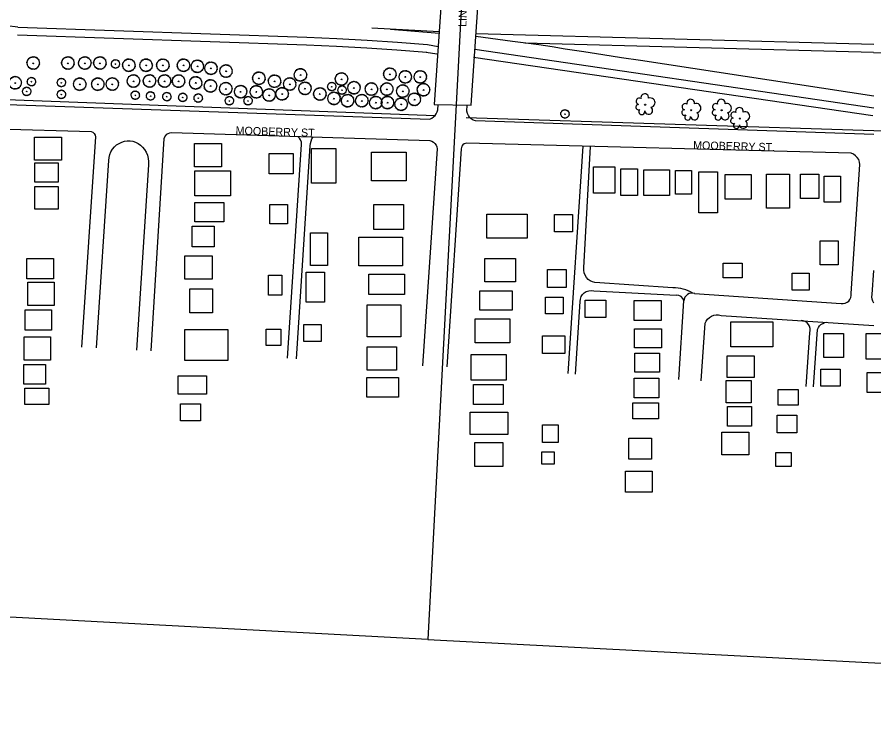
# Model space of a CAD drawing. Extents: x -9648 to 41057, y -12373 to 40276.
# Drawn here: x 13475 to 14546, y -5975 to -5099 of the extents above; entities that cross this region are included whole.
import ezdxf

# ---------------------------------------------------------------- set-up
doc = ezdxf.new("R2010")
doc.units = 0
for name, color, linetype in [('Default', 7, 'Continuous'), ('SC_Scratch1', 7, 'Continuous'), ('SH_Data', 7, 'Continuous')]:
    doc.layers.add(name, color=color, linetype=linetype)

# ---------------------------------------------------------------- blocks, each defined once
blk = doc.blocks.new('15_PIN')
at = {"layer": 'Default'}
for p, q in [((-2.8, 0), (2.8, 0)), ((0, 2.8), (0, -2.8))]:
    blk.add_line(p, q, dxfattribs=at)
for centre, start, end in [((-25.5, 4.5), 275.99, 64.01), ((-25.9, -1.5), 289.3234, 77.3433), ((-23.8, 10.3), 262.6567, 50.6766), ((-20.8, 15.5), 249.3234, 37.3433), ((-16.7, 19.8), 235.99, 24.01), ((-11.6, 23.2), 222.6567, 10.6766), ((-6, 25.2), 209.3234, 357.3433), ((0, 25.9), 195.99, 344.01), ((6, 25.2), 182.6567, 330.6766), ((11.6, 23.2), 169.3234, 317.3433), ((16.7, 19.8), 155.99, 304.01), ((20.8, 15.5), 142.6567, 290.6766), ((23.8, 10.3), 129.3234, 277.3433), ((25.5, 4.5), 115.99, 264.01), ((25.9, -1.5), 102.6567, 250.6766), ((-24.8, -7.4), 302.6567, 90.6766), ((-22.4, -13), 315.99, 104.01), ((-18.8, -17.8), 329.3234, 117.3433), ((-14.2, -21.6), 342.6567, 130.6766), ((-8.9, -24.3), 355.99, 144.01), ((-3, -25.7), 9.3234, 157.3433), ((3, -25.7), 22.6567, 170.6766), ((8.9, -24.3), 35.99, 184.01), ((14.2, -21.6), 49.3234, 197.3433), ((18.8, -17.8), 62.6567, 210.6767), ((22.4, -13), 75.99, 224.01), ((24.8, -7.4), 89.3234, 237.3433)]:
    blk.add_arc(centre, 3.05, start, end, dxfattribs=at)

msp = doc.modelspace()

# ---------------------------------------------------------------- linework, layer by layer
at = {"layer": 'SC_Scratch1'}
for p, q in [((14069.8, -4338.8), (13988.6, -5876.7)), ((14069.8, -4338.8), (13988.6, -5876.7)), ((14069.8, -4338.8), (13988.6, -5876.7)), ((13988.6, -5876.7), (12411.7, -5793.4)), ((13988.6, -5876.7), (15846.2, -5974.8))]:
    msp.add_line(p, q, dxfattribs=at)
at = {"layer": 'SH_Data'}
for p, q in [((14016.7, -4912.3), (13996.7, -5208.5)), ((14042.7, -5209.3), (14062.9, -4912.9)), ((13476.1, -5111.5), (13462.3, -5110)), ((13476.1, -5111.5), (13837.3, -5124.3)), ((13918.7, -5112.5), (14002.9, -5117.1)), ((14002.7, -5119.4), (13941.9, -5114.7)), ((13836.9, -5134.3), (13475.7, -5121.5)), ((13837.3, -5124.3), (13875.1, -5125.9)), ((13875.1, -5125.9), (13912.9, -5127.9)), ((13912.9, -5127.9), (13950.6, -5130.5)), ((14094.5, -5129.7), (14048.6, -5123.5)), ((14546.1, -5133.5), (14048.8, -5119.9)), ((13874.7, -5135.9), (13836.9, -5134.3)), ((13912.3, -5137.8), (13874.5, -5135.8)), ((13949.9, -5140.4), (13912.2, -5137.8)), ((13950.6, -5130.5), (13988.3, -5133.5)), ((13988.3, -5133.5), (14001.6, -5135.7)), ((14111, -5131.7), (14094.5, -5129.7)), ((14545.8, -5143.5), (14110, -5131.5)), ((14127.5, -5133.9), (14111, -5131.7)), ((14143.9, -5136.4), (14127.5, -5133.9)), ((14160.3, -5139.1), (14143.9, -5136.4)), ((14183.8, -5142.6), (14160.3, -5139.1)), ((13987.5, -5143.4), (13949.8, -5140.4)), ((13999.9, -5145.5), (13986.6, -5143.3)), ((14544.6, -5222.6), (14045.9, -5149.6)), ((14546.1, -5212.7), (14047.4, -5139.7)), ((14207.3, -5146.1), (14183.8, -5142.6)), ((14230.8, -5149.8), (14207.3, -5146.1)), ((14254.3, -5153.5), (14230.8, -5149.8)), ((14545.8, -5143.5), (15004.6, -5156.7)), ((14546.1, -5197.7), (14254.3, -5153.5)), ((12857.6, -5180.1), (13997.6, -5221.9)), ((12865.7, -5187.5), (13991.1, -5226.5)), ((13996.7, -5208.5), (14042.7, -5209.3)), ((14001.3, -5214.9), (14001.7, -5208.6)), ((14037.5, -5216.7), (14037.7, -5209.2)), ((13993.5, -5225.3), (13995.7, -5223.8)), ((13995.7, -5223.8), (13997.6, -5222)), ((13997.6, -5222), (13999.2, -5219.8)), ((13999.2, -5219.8), (14000.5, -5217.4)), ((14000.5, -5217.4), (14001.3, -5214.9)), ((14036.6, -5224.5), (14559, -5241.4)), ((14038.1, -5219.5), (14037.5, -5216.7)), ((14039.3, -5222), (14038.1, -5219.5)), ((14040.9, -5224.3), (14039.3, -5222)), ((14043, -5226.3), (14040.9, -5224.3)), ((13212.5, -5232.9), (13567.7, -5241.9)), ((13991.1, -5226.5), (13993.5, -5225.3)), ((14045.4, -5227.7), (14043, -5226.3)), ((14048.1, -5228.7), (14045.4, -5227.7)), ((14546.1, -5245.9), (14048.1, -5228.7)), ((13567.7, -5241.9), (13569.9, -5242.9)), ((13569.9, -5242.9), (13571.7, -5244.5)), ((13571.7, -5244.5), (13572.8, -5246.5)), ((13572.8, -5246.5), (13573.3, -5248.9)), ((13661, -5247.1), (13662.5, -5245.5)), ((13662.5, -5245.5), (13664.2, -5244.4)), ((13664.2, -5244.4), (13666.2, -5243.6)), ((13666.2, -5243.6), (13668.3, -5243.3)), ((13668.3, -5243.3), (13991.1, -5253.3)), ((13573.3, -5248.9), (13556, -5511.6)), ((13599.7, -5258.9), (13602.7, -5256.9)), ((13602.7, -5256.9), (13606.1, -5255.3)), ((13606.1, -5255.3), (13609.5, -5254.3)), ((13609.5, -5254.3), (13613, -5253.7)), ((13613, -5253.7), (13616.5, -5253.8)), ((13616.5, -5253.8), (13620, -5254.3)), ((13620, -5254.3), (13623.3, -5255.4)), ((13623.3, -5255.4), (13626.5, -5257)), ((13626.5, -5257), (13629.4, -5259)), ((13642.7, -5516.3), (13659.3, -5250.9)), ((13659.3, -5250.9), (13659.9, -5248.9)), ((13659.9, -5248.9), (13661, -5247.1)), ((13828.1, -5250.2), (13826, -5248.2)), ((13829.6, -5252.6), (13828.1, -5250.2)), ((13830.6, -5255.3), (13829.6, -5252.6)), ((13830.9, -5258.1), (13830.6, -5255.3)), ((13841.7, -5259.9), (13842, -5256.9)), ((13842, -5256.9), (13842.7, -5254.1)), ((13842.7, -5254.1), (13843.8, -5251.3)), ((13843.8, -5251.3), (13845.3, -5248.8)), ((13991.1, -5253.3), (13993.5, -5254)), ((13993.5, -5254), (13995.7, -5255.2)), ((13995.7, -5255.2), (13997.5, -5257)), ((13997.5, -5257), (13998.9, -5259)), ((14035.6, -5256.9), (14033.9, -5257.6)), ((14037.5, -5256.7), (14035.6, -5256.9)), ((14517.7, -5269.3), (14037.5, -5256.7)), ((13591.2, -5270.8), (13592.6, -5267.4)), ((13592.6, -5267.4), (13594.5, -5264.2)), ((13594.5, -5264.2), (13596.9, -5261.4)), ((13596.9, -5261.4), (13599.7, -5258.9)), ((13629.4, -5259), (13631.9, -5261.5)), ((13631.9, -5261.5), (13634.5, -5264.6)), ((13634.5, -5264.6), (13636.7, -5268)), ((13813.3, -5525.5), (13830.9, -5258.1)), ((13824.4, -5526.1), (13841.7, -5259.9)), ((14000.1, -5263.9), (13982.1, -5534.7)), ((13998.9, -5259), (13999.8, -5261.4)), ((13999.8, -5261.4), (14000.1, -5263.9)), ((14030.5, -5263.9), (14012.2, -5536.3)), ((14030.7, -5262), (14030.5, -5263.9)), ((14031.3, -5260.3), (14030.7, -5262)), ((14032.4, -5258.8), (14031.3, -5260.3)), ((14033.9, -5257.6), (14032.4, -5258.8)), ((14182.2, -5260.5), (14163.5, -5544.5)), ((14183.7, -5412.3), (14191.9, -5260.7)), ((13574.4, -5512.6), (13589.9, -5278.1)), ((13589.9, -5278.1), (13590.3, -5274.4)), ((13590.3, -5274.4), (13591.2, -5270.8)), ((13636.7, -5268), (13638.3, -5271.7)), ((13638.3, -5271.7), (13639.3, -5275.6)), ((13639.3, -5275.6), (13639.7, -5279.7)), ((14520.6, -5270.5), (14517.7, -5269.3)), ((14523.2, -5272.3), (14520.6, -5270.5)), ((14525.4, -5274.6), (14523.2, -5272.3)), ((14527.1, -5277.2), (14525.4, -5274.6)), ((14528.2, -5280.2), (14527.1, -5277.2)), ((13639.5, -5283.7), (13624.5, -5515.3)), ((13639.7, -5279.7), (13639.5, -5283.7)), ((14517.9, -5444.7), (14528.7, -5283.3)), ((14528.7, -5283.3), (14528.2, -5280.2)), ((14183.6, -5415.5), (14183.7, -5412.3)), ((14184.1, -5418.6), (14183.6, -5415.5)), ((14544.1, -5445.9), (14546.1, -5415.7)), ((14185.2, -5421.7), (14184.1, -5418.6)), ((14186.8, -5424.4), (14185.2, -5421.7)), ((14189, -5426.8), (14186.8, -5424.4)), ((14191.5, -5428.7), (14189, -5426.8)), ((14194.4, -5430.1), (14191.5, -5428.7)), ((14197.5, -5430.9), (14194.4, -5430.1)), ((14294.9, -5437.3), (14197.5, -5430.9)), ((14179.3, -5451.4), (14180.3, -5448.4)), ((14180.3, -5448.4), (14181.9, -5445.8)), ((14181.9, -5445.8), (14184.1, -5443.5)), ((14184.1, -5443.5), (14186.7, -5441.9)), ((14186.7, -5441.9), (14189.7, -5441)), ((14189.7, -5441), (14192.8, -5440.8)), ((14192.8, -5440.8), (14195.9, -5441.3)), ((14195.9, -5441.3), (14298.9, -5446.5)), ((14322.1, -5444.3), (14505.3, -5457.1)), ((14516.2, -5452), (14517.3, -5449.7)), ((14517.3, -5449.7), (14517.9, -5447.2)), ((14517.9, -5447.2), (14517.9, -5444.7)), ((14543.7, -5448.7), (14544.1, -5445.9)), ((14543.9, -5451.4), (14543.7, -5448.7)), ((14173.1, -5545.1), (14179.1, -5454.5)), ((14179.1, -5454.5), (14179.3, -5451.4)), ((14302.4, -5552.1), (14308.7, -5453.7)), ((14505.3, -5457.1), (14507.8, -5457.1)), ((14507.8, -5457.1), (14510.3, -5456.6)), ((14510.3, -5456.6), (14512.6, -5455.5)), ((14512.6, -5455.5), (14514.6, -5453.9)), ((14514.6, -5453.9), (14516.2, -5452)), ((14544.7, -5454.1), (14543.9, -5451.4)), ((14546.1, -5456.5), (14544.7, -5454.1)), ((14346, -5471.7), (14349, -5471.1)), ((14349, -5471.1), (14352.1, -5471.2)), ((14352.1, -5471.2), (14355.1, -5471.9)), ((14330.2, -5553.6), (14335.1, -5481.7)), ((14335.1, -5481.7), (14336.4, -5478.9)), ((14336.4, -5478.9), (14338.2, -5476.4)), ((14338.2, -5476.4), (14340.5, -5474.3)), ((14340.5, -5474.3), (14343.1, -5472.7)), ((14343.1, -5472.7), (14346, -5471.7)), ((14355.1, -5471.9), (14546.1, -5484.3)), ((14457.9, -5478.5), (14455.2, -5478.1)), ((14460.4, -5479.5), (14457.9, -5478.5)), ((14462.6, -5481.1), (14460.4, -5479.5)), ((14464.4, -5483.1), (14462.6, -5481.1)), ((14480, -5483.4), (14482.1, -5482)), ((14482.1, -5482), (14484.3, -5480.9)), ((14484.3, -5480.9), (14486.7, -5480.2)), ((14465.7, -5485.5), (14464.4, -5483.1)), ((14466.4, -5488.1), (14465.7, -5485.5)), ((14465.9, -5493.5), (14466.5, -5490.8)), ((14466.5, -5490.8), (14466.4, -5488.1)), ((14470.7, -5561.2), (14475.7, -5489.3)), ((14475.7, -5489.3), (14476.8, -5487.1)), ((14476.8, -5487.1), (14478.2, -5485.1)), ((14478.2, -5485.1), (14480, -5483.4)), ((14461.5, -5560.7), (14465.9, -5493.5))]:
    msp.add_line(p, q, dxfattribs=at)
for points in [[(13497, -5249.3), (13530.8, -5249.3), (13530.8, -5277.7), (13497, -5277.7)], [(13696.9, -5256.9), (13730.6, -5256.9), (13730.6, -5286.1), (13696.9, -5286.1)], [(13843.1, -5263.2), (13873.6, -5263.2), (13873.6, -5306.5), (13843.1, -5306.5)], [(13918.1, -5267.7), (13961.4, -5267.7), (13961.4, -5303.9), (13918.1, -5303.9)], [(13790.3, -5269.6), (13820.2, -5269.6), (13820.2, -5295), (13790.3, -5295)], [(13497.6, -5281.3), (13526.6, -5281.3), (13526.6, -5305.5), (13497.6, -5305.5)], [(14195.5, -5286.1), (14222.3, -5286.1), (14222.3, -5319.3), (14195.5, -5319.3)], [(14229.8, -5288.7), (14250.7, -5288.7), (14250.7, -5322), (14229.8, -5322)], [(13697.5, -5291.2), (13742, -5291.2), (13742, -5322.4), (13697.5, -5322.4)], [(14258.7, -5289.8), (14290.8, -5289.8), (14290.8, -5322), (14258.7, -5322)], [(14298.3, -5290.9), (14318.1, -5290.9), (14318.1, -5320.3), (14298.3, -5320.3)], [(14327.2, -5292.5), (14350.8, -5292.5), (14350.8, -5343.9), (14327.2, -5343.9)], [(14360.4, -5295.7), (14392.6, -5295.7), (14392.6, -5326.8), (14360.4, -5326.8)], [(14411.8, -5295.2), (14440.8, -5295.2), (14440.8, -5338), (14411.8, -5338)], [(14454.2, -5295.2), (14477.2, -5295.2), (14477.2, -5325.7), (14454.2, -5325.7)], [(14484.1, -5297.9), (14504.5, -5297.9), (14504.5, -5330.5), (14484.1, -5330.5)], [(13497.6, -5310.9), (13526.6, -5310.9), (13526.6, -5339.3), (13497.6, -5339.3)], [(13697.5, -5330.6), (13733.7, -5330.6), (13733.7, -5354.8), (13697.5, -5354.8)], [(13791, -5333.2), (13813.2, -5333.2), (13813.2, -5357.4), (13791, -5357.4)], [(13921.3, -5333.2), (13958.2, -5333.2), (13958.2, -5364.4), (13921.3, -5364.4)], [(14062.4, -5345.3), (14112.7, -5345.3), (14112.7, -5375.2), (14062.4, -5375.2)], [(14147, -5345.9), (14169.3, -5345.9), (14169.3, -5367.5), (14147, -5367.5)], [(13694.3, -5360.5), (13721.7, -5360.5), (13721.7, -5386), (13694.3, -5386)], [(13841.8, -5368.8), (13863.4, -5368.8), (13863.4, -5409.5), (13841.8, -5409.5)], [(13902.2, -5373.9), (13956.9, -5373.9), (13956.9, -5410.1), (13902.2, -5410.1)], [(14478.8, -5378.7), (14501.3, -5378.7), (14501.3, -5408.7), (14478.8, -5408.7)], [(13487.4, -5400.9), (13520.6, -5400.9), (13520.6, -5426.3), (13487.4, -5426.3)], [(13684.8, -5397.4), (13719.1, -5397.4), (13719.1, -5426.7), (13684.8, -5426.7)], [(14059.9, -5400.6), (14098.1, -5400.6), (14098.1, -5429.9), (14059.9, -5429.9)], [(14357.8, -5406.6), (14381.3, -5406.6), (14381.3, -5424.8), (14357.8, -5424.8)], [(13836.7, -5417.8), (13859.6, -5417.8), (13859.6, -5455.3), (13836.7, -5455.3)], [(14138.1, -5414.6), (14161.6, -5414.6), (14161.6, -5436.9), (14138.1, -5436.9)], [(13789.7, -5421.6), (13806.2, -5421.6), (13806.2, -5446.4), (13789.7, -5446.4)], [(13914.9, -5420.3), (13959.4, -5420.3), (13959.4, -5445.8), (13914.9, -5445.8)], [(14444, -5418.9), (14465.4, -5418.9), (14465.4, -5440.3), (14444, -5440.3)], [(13488.6, -5430.5), (13521.8, -5430.5), (13521.8, -5459.5), (13488.6, -5459.5)], [(13691.1, -5438.8), (13719.7, -5438.8), (13719.7, -5468.7), (13691.1, -5468.7)], [(14053.5, -5441.3), (14094.2, -5441.3), (14094.2, -5465.5), (14053.5, -5465.5)], [(14135.6, -5448.9), (14157.8, -5448.9), (14157.8, -5469.9), (14135.6, -5469.9)], [(13913, -5458.5), (13955, -5458.5), (13955, -5498.6), (13913, -5498.6)], [(14185.3, -5452.7), (14211, -5452.7), (14211, -5474.6), (14185.3, -5474.6)], [(14246.4, -5453.2), (14280.1, -5453.2), (14280.1, -5478.4), (14246.4, -5478.4)], [(13485.5, -5465), (13518.2, -5465), (13518.2, -5490.3), (13485.5, -5490.3)], [(14047.8, -5476.3), (14091.1, -5476.3), (14091.1, -5506.2), (14047.8, -5506.2)], [(14367.4, -5480), (14419.9, -5480), (14419.9, -5511), (14367.4, -5511)], [(13684.8, -5489.6), (13738.8, -5489.6), (13738.8, -5528.4), (13684.8, -5528.4)], [(13786.5, -5489), (13804.9, -5489), (13804.9, -5509.4), (13786.5, -5509.4)], [(13833.6, -5483.3), (13855.2, -5483.3), (13855.2, -5504.3), (13833.6, -5504.3)], [(14246.9, -5488.5), (14280.7, -5488.5), (14280.7, -5512.6), (14246.9, -5512.6)], [(13484.3, -5498.8), (13516.9, -5498.8), (13516.9, -5527.8), (13484.3, -5527.8)], [(14131.8, -5497.3), (14159.7, -5497.3), (14159.7, -5519.5), (14131.8, -5519.5)], [(14483.6, -5494.4), (14508.2, -5494.4), (14508.2, -5524.4), (14483.6, -5524.4)], [(14536.6, -5494.4), (14591.8, -5494.4), (14591.8, -5526.6), (14536.6, -5526.6)], [(13913, -5511.3), (13949.3, -5511.3), (13949.3, -5540.5), (13913, -5540.5)], [(14042.7, -5520.8), (14086.6, -5520.8), (14086.6, -5552.6), (14042.7, -5552.6)], [(14247.5, -5519.1), (14278, -5519.1), (14278, -5542.6), (14247.5, -5542.6)], [(14362.6, -5522.3), (14396.3, -5522.3), (14396.3, -5549.6), (14362.6, -5549.6)], [(13483.7, -5533.2), (13510.9, -5533.2), (13510.9, -5558), (13483.7, -5558)], [(14479.9, -5538.9), (14503.9, -5538.9), (14503.9, -5560.3), (14479.9, -5560.3)], [(14537.7, -5543.2), (14572, -5543.2), (14572, -5568.4), (14537.7, -5568.4)], [(13676.5, -5547.5), (13712.1, -5547.5), (13712.1, -5570.4), (13676.5, -5570.4)], [(13912.4, -5549.4), (13951.8, -5549.4), (13951.8, -5574.2), (13912.4, -5574.2)], [(14246.4, -5550.1), (14277.4, -5550.1), (14277.4, -5574.8), (14246.4, -5574.8)], [(14361.5, -5553.4), (14392.6, -5553.4), (14392.6, -5581.2), (14361.5, -5581.2)], [(13484.9, -5562.8), (13515.1, -5562.8), (13515.1, -5583.4), (13484.9, -5583.4)], [(14045.9, -5558.3), (14082.8, -5558.3), (14082.8, -5583.1), (14045.9, -5583.1)], [(14426.3, -5564.6), (14451.5, -5564.6), (14451.5, -5583.9), (14426.3, -5583.9)], [(13679.7, -5582.5), (13704.5, -5582.5), (13704.5, -5603.5), (13679.7, -5603.5)], [(14244.8, -5581.2), (14276.9, -5581.2), (14276.9, -5601), (14244.8, -5601)], [(14363.1, -5585.5), (14393.1, -5585.5), (14393.1, -5610.1), (14363.1, -5610.1)], [(14041.5, -5592.7), (14088.5, -5592.7), (14088.5, -5620.7), (14041.5, -5620.7)], [(14425.2, -5596.7), (14449.9, -5596.7), (14449.9, -5618.7), (14425.2, -5618.7)], [(14131.8, -5608.6), (14151.5, -5608.6), (14151.5, -5630.8), (14131.8, -5630.8)], [(14356.2, -5617.6), (14389.9, -5617.6), (14389.9, -5646), (14356.2, -5646)], [(14047.2, -5630.8), (14082.2, -5630.8), (14082.2, -5660.7), (14047.2, -5660.7)], [(14240, -5625.1), (14268.3, -5625.1), (14268.3, -5651.4), (14240, -5651.4)], [(14131.1, -5642.3), (14146.4, -5642.3), (14146.4, -5657.6), (14131.1, -5657.6)], [(14423.6, -5643.3), (14442.9, -5643.3), (14442.9, -5660.5), (14423.6, -5660.5)], [(14235.7, -5666.4), (14268.9, -5666.4), (14268.9, -5692.6), (14235.7, -5692.6)]]:
    msp.add_lwpolyline(points, close=True, dxfattribs=at)
for centre in [(14260.3, -5208.6), (14317.7, -5215.5), (14355.8, -5215.5), (14378.6, -5225.9)]:
    msp.add_circle(centre, 0.71, dxfattribs=at)
for centre, radius, start, end in [((14252.9, -5204.3), 3.94, 56.6142, 257.8219), ((14259.8, -5199.8), 4.86, 351.9296, 194.2439), ((14266.8, -5205.9), 5.79, 277.7319, 112.2414), ((14317.2, -5206.7), 4.86, 351.9296, 194.2439), ((14355.3, -5206.7), 4.86, 351.9296, 194.2439), ((14251.9, -5211.5), 3.34, 86.789, 298.7584), ((14264.6, -5215.6), 5.01, 188.9565, 53.358), ((14310.3, -5211.2), 3.94, 56.6142, 257.8219), ((14324.2, -5212.8), 5.79, 277.7319, 112.2414), ((14348.4, -5211.2), 3.94, 56.6142, 257.8219), ((14362.3, -5212.8), 5.79, 277.7319, 112.2414), ((14378.1, -5217.1), 4.86, 351.9296, 194.2439), ((14256, -5217.2), 3.73, 131.8468, 12.3255), ((14309.3, -5218.4), 3.34, 86.789, 298.7584), ((14313.4, -5224.1), 3.73, 131.8468, 12.3255), ((14322, -5222.5), 5.01, 188.9565, 53.358), ((14347.4, -5218.4), 3.34, 86.789, 298.7584), ((14351.5, -5224.1), 3.73, 131.8468, 12.3255), ((14360.1, -5222.5), 5.01, 188.9565, 53.358), ((14371.2, -5221.6), 3.94, 56.6142, 257.8219), ((14385.1, -5223.2), 5.79, 277.7319, 112.2414), ((14370.2, -5228.8), 3.34, 86.789, 298.7584), ((14374.3, -5234.5), 3.73, 131.8468, 12.3255), ((14382.9, -5232.9), 5.01, 188.9565, 53.358), ((14295.2, -5487.1), 49.8, 60.2, 90.3), ((14299.3, -5456.2), 9.7, 15, 92.4), ((14319.1, -5454.3), 10.4, 73.1, 177)]:
    msp.add_arc(centre, radius, start, end, dxfattribs=at)

# ---------------------------------------------------------------- block references
for p, xscale, yscale, rotation in [((13495.5, -5156.5), 0.32808397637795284, 0.32808397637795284, 64.61472397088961), ((13495.5, -5156.5), 0.32808397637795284, 0.32808397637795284, 64.61472397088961), ((13538.8, -5156.5), 0.32808397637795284, 0.32808397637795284, 64.61472397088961), ((13559.9, -5156.5), 0.32808397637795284, 0.32808397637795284, 64.61472397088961), ((13578.8, -5156.5), 0.32808397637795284, 0.32808397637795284, 64.61472397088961), ((13598.3, -5157.6), 0.22126578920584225, 0.22126578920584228, 64.6147239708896), ((13615, -5159.2), 0.32808397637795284, 0.32808397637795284, 64.61472397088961), ((13615, -5159.2), 0.32808397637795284, 0.32808397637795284, 64.61472397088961), ((13636.5, -5159.2), 0.32808397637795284, 0.32808397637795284, 64.61472397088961), ((13657.5, -5159.2), 0.32808397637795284, 0.32808397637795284, 64.61472397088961), ((13683.3, -5159.3), 0.32808397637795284, 0.32808397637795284, 64.61472397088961), ((13700.6, -5160.6), 0.32808397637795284, 0.32808397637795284, 64.61472397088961), ((13717.6, -5163), 0.32808397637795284, 0.32808397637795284, 64.61472397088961), ((13736.4, -5166.6), 0.32808397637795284, 0.32808397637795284, 64.61472397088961), ((13829.4, -5171.3), 0.32808397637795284, 0.32808397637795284, 64.61472397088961), ((13941.2, -5170.4), 0.32808397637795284, 0.32808397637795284, 64.61472397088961), ((13472.9, -5181.2), 0.32808397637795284, 0.32808397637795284, 64.61472397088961), ((13620.7, -5179), 0.32808397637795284, 0.32808397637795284, 64.61472397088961), ((13640.8, -5179), 0.32808397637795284, 0.32808397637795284, 64.61472397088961), ((13659.6, -5179), 0.32808397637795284, 0.32808397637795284, 64.61472397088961), ((13677.1, -5179.1), 0.32808397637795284, 0.32808397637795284, 64.61472397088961), ((13698.5, -5181.3), 0.32808397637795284, 0.32808397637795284, 64.61472397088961), ((13777.5, -5175.5), 0.32808397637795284, 0.32808397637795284, 64.61472397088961), ((13797.1, -5179.2), 0.32808397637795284, 0.32808397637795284, 64.61472397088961), ((13880.7, -5176.5), 0.32808397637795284, 0.32808397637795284, 64.61472397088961), ((13960.5, -5173.8), 0.32808397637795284, 0.32808397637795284, 64.61472397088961), ((13979.2, -5173.8), 0.32808397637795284, 0.32808397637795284, 64.61472397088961), ((13493.3, -5179.8), 0.22126578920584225, 0.22126578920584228, 64.6147239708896), ((13530.6, -5180.9), 0.22126578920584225, 0.22126578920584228, 64.6147239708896), ((13553.6, -5182.9), 0.32808397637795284, 0.32808397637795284, 64.61472397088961), ((13576.2, -5182.9), 0.32808397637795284, 0.32808397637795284, 64.61472397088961), ((13594.3, -5182.8), 0.32808397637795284, 0.32808397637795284, 64.61472397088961), ((13594.3, -5182.8), 0.32808397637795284, 0.32808397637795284, 64.61472397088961), ((13717, -5185.1), 0.32808397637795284, 0.32808397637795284, 64.61472397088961), ((13736.1, -5188.6), 0.32808397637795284, 0.32808397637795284, 64.61472397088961), ((13754.7, -5192.3), 0.32808397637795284, 0.32808397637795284, 64.61472397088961), ((13774.3, -5192.5), 0.32808397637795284, 0.32808397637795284, 64.61472397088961), ((13816, -5182.8), 0.32808397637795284, 0.32808397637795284, 64.61472397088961), ((13835.1, -5188.2), 0.32808397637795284, 0.32808397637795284, 64.61472397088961), ((13868.6, -5185.9), 0.22126578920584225, 0.22126578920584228, 64.6147239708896), ((13896.3, -5187.4), 0.32808397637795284, 0.32808397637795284, 64.61472397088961), ((13918.1, -5189.1), 0.32808397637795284, 0.32808397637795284, 64.61472397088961), ((13937.4, -5189.1), 0.32808397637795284, 0.32808397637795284, 64.61472397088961), ((13957.3, -5191.6), 0.32808397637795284, 0.32808397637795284, 64.61472397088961), ((13983.2, -5189.9), 0.32808397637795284, 0.32808397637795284, 64.61472397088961), ((13487.3, -5192), 0.22126578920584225, 0.22126578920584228, 64.6147239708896), ((13530.6, -5195.7), 0.22126578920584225, 0.22126578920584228, 64.6147239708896), ((13623, -5196.7), 0.22126578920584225, 0.22126578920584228, 64.6147239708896), ((13623, -5196.7), 0.22126578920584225, 0.22126578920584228, 64.6147239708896), ((13642.1, -5197.6), 0.22126578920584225, 0.22126578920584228, 64.6147239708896), ((13662.5, -5198.5), 0.22126578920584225, 0.22126578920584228, 64.6147239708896), ((13682.3, -5199.4), 0.22126578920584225, 0.22126578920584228, 64.6147239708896), ((13701.7, -5200.3), 0.22126578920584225, 0.22126578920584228, 64.6147239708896), ((13701.7, -5200.3), 0.22126578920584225, 0.22126578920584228, 64.6147239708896), ((13790.3, -5196.5), 0.32808397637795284, 0.32808397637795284, 64.61472397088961), ((13806.5, -5195), 0.32808397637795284, 0.32808397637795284, 64.61472397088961), ((13853.7, -5195.2), 0.32808397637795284, 0.32808397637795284, 64.61472397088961), ((13871.3, -5200.7), 0.32808397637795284, 0.32808397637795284, 64.61472397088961), ((13881.4, -5190.3), 0.22126578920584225, 0.22126578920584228, 64.6147239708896), ((13888.3, -5203.6), 0.32808397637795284, 0.32808397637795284, 64.61472397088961), ((13906.1, -5203.6), 0.32808397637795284, 0.32808397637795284, 64.61472397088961), ((13971.8, -5201.9), 0.32808397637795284, 0.32808397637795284, 64.61472397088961), ((13740.6, -5203.7), 0.22126578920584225, 0.22126578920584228, 64.6147239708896), ((13764, -5203.7), 0.22126578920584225, 0.22126578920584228, 64.6147239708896), ((13923.6, -5205.9), 0.32808397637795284, 0.32808397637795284, 64.61472397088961), ((13938.2, -5205.9), 0.32808397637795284, 0.32808397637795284, 64.61472397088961), ((13955.2, -5208), 0.32808397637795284, 0.32808397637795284, 64.61472397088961), ((14160, -5220.1), 0.22126578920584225, 0.22126578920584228, 64.6147239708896)]:
    msp.add_blockref('15_PIN', p, dxfattribs=dict(at, xscale=xscale, yscale=yscale, rotation=rotation))

# ---------------------------------------------------------------- texts
at = {"layer": 'SC_Scratch1'}
for s, rotation, p in [('LINWOOD AVE', 88.5022, (14036.8, -5111.5)), ('MOOBERRY ST', 358.2256, (13748.3, -5245.7)), ('MOOBERRY ST.', 358.497, (14320.1, -5264))]:
    msp.add_text(s, height=10, rotation=rotation, dxfattribs=at).set_placement(p)

doc.saveas('drawing.dxf')
